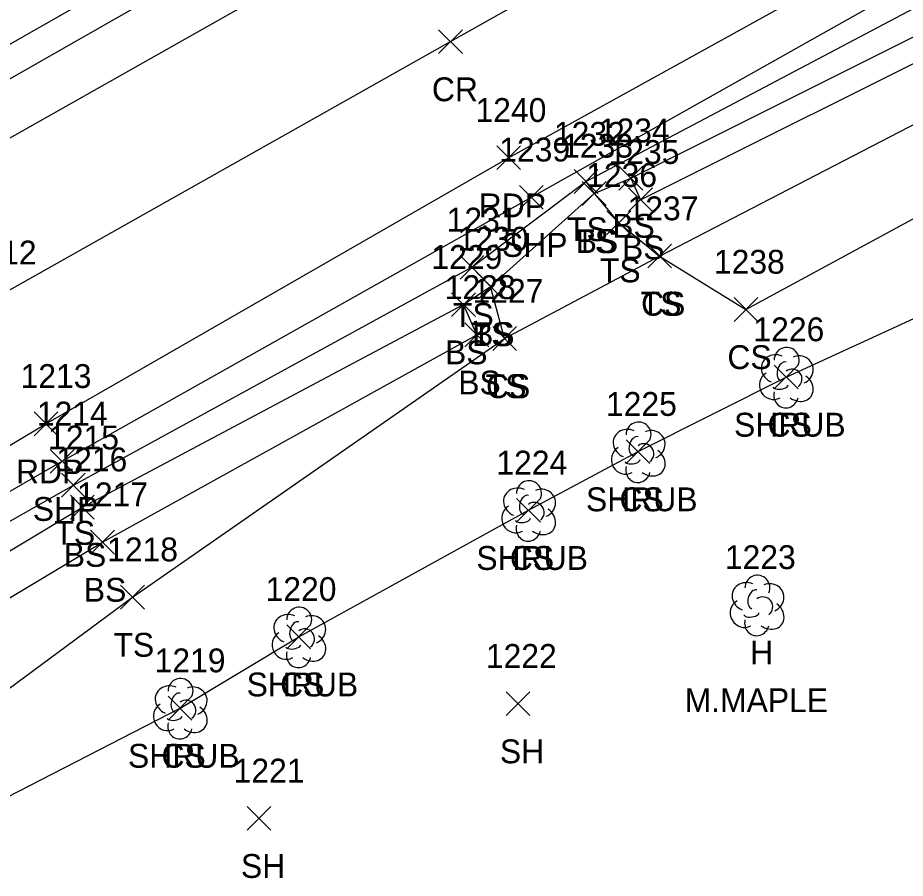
# Model space of a CAD drawing. Extents: x 1606530 to 1613020, y 784959 to 789666.
# Drawn here: x 1608865.5 to 1608940, y 788252.4 to 788324.6 of the extents above; entities that cross this region are included whole.
import ezdxf

# ---------------------------------------------------------------- set-up
doc = ezdxf.new("R2010")
doc.units = 0
for name, color, linetype in [('L_A', 7, 'Continuous'), ('L_C', 7, 'Continuous'), ('L_I', 7, 'Continuous'), ('L_TIC', 7, 'Continuous'), ('LELB', 7, 'Continuous'), ('LSH', 7, 'Continuous'), ('LTD', 7, 'Continuous'), ('P_A', 7, 'Continuous'), ('P_I', 7, 'Continuous'), ('P_TIC', 7, 'Continuous'), ('PET', 7, 'Continuous'), ('PRC', 7, 'Continuous'), ('PSP', 7, 'Continuous')]:
    doc.layers.add(name, color=color, linetype=linetype)

msp = doc.modelspace()

# ---------------------------------------------------------------- linework, layer by layer
at = {"layer": 'L_TIC'}
for points in [[(1608912.174, 788309.86), (1608914.174, 788311.86)], [(1608914.174, 788309.86), (1608912.174, 788311.86)], [(1608912.174, 788309.86), (1608914.174, 788311.86)], [(1608914.174, 788309.86), (1608912.174, 788311.86)], [(1608915.937, 788310.145), (1608917.937, 788312.145)], [(1608917.937, 788310.145), (1608915.937, 788312.145)], [(1608915.937, 788310.145), (1608917.937, 788312.145)], [(1608917.937, 788310.145), (1608915.937, 788312.145)], [(1608912.863, 788308.861), (1608914.863, 788310.861)], [(1608914.863, 788308.861), (1608912.863, 788310.861)], [(1608912.863, 788308.861), (1608914.863, 788310.861)], [(1608914.863, 788308.861), (1608912.863, 788310.861)], [(1608916.754, 788308.334), (1608918.754, 788310.334)], [(1608918.754, 788308.334), (1608916.754, 788310.334)], [(1608914.932, 788306.405), (1608916.932, 788308.405)], [(1608916.932, 788306.405), (1608914.932, 788308.405)], [(1608918.354, 788303.61), (1608920.354, 788305.61)], [(1608920.354, 788303.61), (1608918.354, 788305.61)], [(1608918.354, 788303.61), (1608920.354, 788305.61)], [(1608920.354, 788303.61), (1608918.354, 788305.61)], [(1608902.607, 788302.663), (1608904.607, 788304.663)], [(1608904.607, 788302.663), (1608902.607, 788304.663)], [(1608902.607, 788302.663), (1608904.607, 788304.663)], [(1608904.607, 788302.663), (1608902.607, 788304.663)], [(1608904.174, 788301.06), (1608906.174, 788303.06)], [(1608906.174, 788301.06), (1608904.174, 788303.06)], [(1608904.174, 788301.06), (1608906.174, 788303.06)], [(1608906.174, 788301.06), (1608904.174, 788303.06)], [(1608901.903, 788299.531), (1608903.903, 788301.531)], [(1608903.903, 788299.531), (1608901.903, 788301.531)], [(1608901.903, 788299.531), (1608903.903, 788301.531)], [(1608903.903, 788299.531), (1608901.903, 788301.531)], [(1608925.596, 788299.128), (1608927.596, 788301.128)], [(1608927.596, 788299.128), (1608925.596, 788301.128)], [(1608903.013, 788296.997), (1608905.013, 788298.997)], [(1608905.013, 788296.997), (1608903.013, 788298.997)], [(1608905.345, 788296.69), (1608907.345, 788298.69)], [(1608907.345, 788296.69), (1608905.345, 788298.69)], [(1608905.345, 788296.69), (1608907.345, 788298.69)], [(1608907.345, 788296.69), (1608905.345, 788298.69)], [(1608928.967, 788293.463), (1608930.967, 788295.463)], [(1608930.967, 788293.463), (1608928.967, 788295.463)], [(1608916.542, 788287.203), (1608918.542, 788289.203)], [(1608918.542, 788287.203), (1608916.542, 788289.203)], [(1608869.165, 788284.39), (1608871.165, 788286.39)], [(1608871.165, 788284.39), (1608869.165, 788286.39)], [(1608869.917, 788282.544), (1608871.917, 788284.544)], [(1608871.917, 788282.544), (1608869.917, 788284.544)], [(1608907.345, 788282.283), (1608909.345, 788284.283)], [(1608909.345, 788282.283), (1608907.345, 788284.283)], [(1608871.6, 788279.617), (1608873.6, 788281.617)], [(1608873.6, 788279.617), (1608871.6, 788281.617)], [(1608874.117, 788275.001), (1608876.117, 788277.001)], [(1608876.117, 788275.001), (1608874.117, 788277.001)], [(1608888.068, 788271.674), (1608890.068, 788273.674)], [(1608890.068, 788271.674), (1608888.068, 788273.674)], [(1608878.114, 788265.692), (1608880.114, 788267.692)], [(1608880.114, 788265.692), (1608878.114, 788267.692)], [(1608906.464, 788266.065), (1608908.464, 788268.065)], [(1608908.464, 788266.065), (1608906.464, 788268.065)], [(1608884.736, 788256.449), (1608886.736, 788258.449)], [(1608886.736, 788256.449), (1608884.736, 788258.449)]]:
    msp.add_lwpolyline(points, dxfattribs=at)
at = {"layer": 'LELB'}
for points in [[(1608830.696, 788263.063), (1608870.165, 788285.39), (1608903.607, 788303.663), (1608913.174, 788310.86), (1608944.686, 788327.514), (1608982.087, 788348.333), (1609025.652, 788367.839), (1609062.434, 788383.436), (1609080.361, 788388.448), (1609093.562, 788391.85), (1609111.494, 788398.335), (1609124.294, 788403.549), (1609165.327, 788413.887), (1609196.534, 788419.382), (1609241.91, 788424.939), (1609287.826, 788428.62), (1609331.16, 788428.802), (1609379.004, 788428.227), (1609424.692, 788425.716), (1609443.901, 788424.449), (1609475.845, 788418.568), (1609486.477, 788419.986), (1609502.626, 788421.703)], [(1608831.711, 788260.016), (1608870.917, 788283.544), (1608902.903, 788300.531), (1608905.174, 788302.06), (1608913.863, 788309.861), (1608916.937, 788311.145), (1608945.63, 788325.493), (1608982.977, 788345.361), (1609026.683, 788366.486), (1609062.425, 788381.051), (1609095.627, 788388.111), (1609108.106, 788392.394), (1609116.71, 788392.112), (1609124.652, 788392.268)], [(1608916.937, 788311.145), (1608917.754, 788309.334), (1608946.535, 788323.696), (1608983.532, 788344.076), (1609027.167, 788365.399), (1609062.769, 788379.31), (1609096.646, 788386.547), (1609108.627, 788390.006), (1609115.481, 788389.157)], [(1608913.174, 788310.86), (1608913.863, 788309.861), (1608915.932, 788307.405), (1608919.354, 788304.61), (1608948.758, 788319.84), (1608984.788, 788341.433), (1609027.872, 788364.143), (1609064.518, 788375.718), (1609081.683, 788376.845), (1609097.263, 788381.318)], [(1608906.345, 788297.69), (1608919.354, 788304.61), (1608926.596, 788300.128), (1608951.558, 788313.661), (1608958.57, 788316.223), (1608987.922, 788332.405), (1609030.947, 788357.96), (1609064.344, 788369.211), (1609081.683, 788376.845)], [(1608853.861, 788253.713), (1608879.114, 788266.692), (1608889.068, 788272.674), (1608908.345, 788283.283), (1608917.542, 788288.203), (1608929.967, 788294.463), (1608949.674, 788303.496), (1608962.876, 788306.16), (1608991.964, 788321.509), (1609035.123, 788349.675), (1609066.903, 788360.544), (1609090.163, 788369.421)], [(1608811.684, 788290.669), (1608854.482, 788316.493), (1608894.214, 788339.177), (1608933.711, 788362.091)], [(1608849.379, 788256.992), (1608875.117, 788276.001), (1608906.345, 788297.69), (1608905.174, 788302.06), (1608903.607, 788303.663)], [(1608833.879, 788257.4), (1608872.6, 788280.617), (1608904.013, 788297.997), (1608902.903, 788300.531)]]:
    msp.add_lwpolyline(points, dxfattribs=at)
at = {"layer": 'LSH'}
for p, q in [((1608929.967, 788294.463), (1608929.967, 788294.463)), ((1608929.967, 788294.463), (1608929.967, 788294.463)), ((1608917.542, 788288.203), (1608917.542, 788288.203)), ((1608917.542, 788288.203), (1608917.542, 788288.203)), ((1608908.345, 788283.283), (1608908.345, 788283.283)), ((1608908.345, 788283.283), (1608908.345, 788283.283)), ((1608889.068, 788272.674), (1608889.068, 788272.674)), ((1608889.068, 788272.674), (1608889.068, 788272.674)), ((1608879.114, 788266.692), (1608879.114, 788266.692)), ((1608879.114, 788266.692), (1608879.114, 788266.692))]:
    msp.add_line(p, q, dxfattribs=at)
for centre in [(1608930.013, 788295.897), (1608917.589, 788289.637), (1608908.392, 788284.717), (1608889.115, 788274.108), (1608879.16, 788268.126)]:
    msp.add_arc(centre, 1.047, 335.52715, 180.95627, dxfattribs=at)
for centre, major_axis, ratio, start_param, end_param in [((1608929.175, 788295.13), (1.21, -0.512), 0.895232, 1.570796, 4.712389), ((1608929.758, 788294.921), (-0.208, -0.792), 0.645439, 3.141593, 6.283185), ((1608931.008, 788295.047), (-1.141, -0.483), 0.949671, 1.570796, 4.712389), ((1608930.467, 788294.297), (-0.5, 0.667), 0.989748, 3.141593, 6.283185), ((1608928.883, 788293.755), (0.584, -1.042), 0.959034, 3.141593, 6.283185), ((1608930.967, 788293.63), (-1.09, 0.792), 0.841452, 1.570796, 4.712389), ((1608929.508, 788293.713), (-0.625, -0.083), 0.423636, 0, 3.141593), ((1608929.967, 788292.963), (0.265, 1.061), 0.942809, 1.570796, 4.712389), ((1608916.751, 788288.87), (1.21, -0.512), 0.895232, 1.570796, 4.712389), ((1608918.584, 788288.787), (-1.141, -0.483), 0.949671, 1.570796, 4.712389), ((1608917.334, 788288.662), (-0.208, -0.792), 0.645439, 3.141593, 6.283185), ((1608916.459, 788287.495), (0.584, -1.042), 0.959034, 3.141593, 6.283185), ((1608918.042, 788288.037), (-0.5, 0.667), 0.989748, 3.141593, 6.283185), ((1608918.543, 788287.37), (-1.09, 0.792), 0.841452, 1.570796, 4.712389), ((1608917.543, 788286.703), (0.265, 1.061), 0.942809, 1.570796, 4.712389), ((1608917.084, 788287.453), (-0.625, -0.083), 0.423636, 0, 3.141593), ((1608907.553, 788283.949), (1.21, -0.512), 0.895232, 1.570796, 4.712389), ((1608908.137, 788283.741), (-0.208, -0.792), 0.645439, 3.141593, 6.283185), ((1608909.386, 788283.866), (-1.141, -0.483), 0.949671, 1.570796, 4.712389), ((1608908.845, 788283.116), (-0.5, 0.667), 0.989748, 3.141593, 6.283185), ((1608907.262, 788282.574), (0.584, -1.042), 0.959034, 3.141593, 6.283185), ((1608909.345, 788282.45), (-1.09, 0.792), 0.841452, 1.570796, 4.712389), ((1608907.887, 788282.533), (-0.625, -0.083), 0.423636, 0, 3.141593), ((1608908.345, 788281.783), (0.265, 1.061), 0.942809, 1.570796, 4.712389), ((1608888.276, 788273.34), (1.21, -0.512), 0.895232, 1.570796, 4.712389), ((1608890.11, 788273.257), (-1.141, -0.483), 0.949671, 1.570796, 4.712389), ((1608888.86, 788273.132), (-0.208, -0.792), 0.645439, 3.141593, 6.283185), ((1608889.568, 788272.507), (-0.5, 0.667), 0.989748, 3.141593, 6.283185), ((1608887.985, 788271.965), (0.584, -1.042), 0.959034, 3.141593, 6.283185), ((1608890.068, 788271.84), (-1.09, 0.792), 0.841452, 1.570796, 4.712389), ((1608888.61, 788271.924), (-0.625, -0.083), 0.423636, 0, 3.141593), ((1608889.068, 788271.174), (0.265, 1.061), 0.942809, 1.570796, 4.712389), ((1608878.322, 788267.359), (1.21, -0.512), 0.895232, 1.570796, 4.712389), ((1608880.155, 788267.276), (-1.141, -0.483), 0.949671, 1.570796, 4.712389), ((1608878.905, 788267.15), (-0.208, -0.792), 0.645439, 3.141593, 6.283185), ((1608878.03, 788265.983), (0.584, -1.042), 0.959034, 3.141593, 6.283185), ((1608879.614, 788266.525), (-0.5, 0.667), 0.989748, 3.141593, 6.283185), ((1608880.114, 788265.859), (-1.09, 0.792), 0.841452, 1.570796, 4.712389), ((1608878.655, 788265.942), (-0.625, -0.083), 0.423636, 0, 3.141593), ((1608879.114, 788265.192), (0.265, 1.061), 0.942809, 1.570796, 4.712389)]:
    msp.add_ellipse(centre, major_axis=major_axis, ratio=ratio, start_param=start_param, end_param=end_param, dxfattribs=at)
at = {"layer": 'LTD'}
msp.add_line((1608927.515, 788275.352), (1608927.515, 788275.352), dxfattribs=at)
msp.add_line((1608927.515, 788275.352), (1608927.515, 788275.352), dxfattribs=at)
msp.add_arc((1608927.561, 788276.786), 1.047, 335.52715, 180.95627, dxfattribs=at)
for centre, major_axis, ratio, start_param, end_param in [((1608926.723, 788276.018), (1.21, -0.512), 0.895232, 1.570796, 4.712389), ((1608928.556, 788275.935), (-1.141, -0.483), 0.949671, 1.570796, 4.712389), ((1608927.306, 788275.81), (-0.208, -0.792), 0.645439, 3.141593, 6.283185), ((1608926.431, 788274.643), (0.584, -1.042), 0.959034, 3.141593, 6.283185), ((1608928.015, 788275.185), (-0.5, 0.667), 0.989748, 3.141593, 6.283185), ((1608928.515, 788274.518), (-1.09, 0.792), 0.841452, 1.570796, 4.712389), ((1608927.056, 788274.601), (-0.625, -0.083), 0.423636, 0, 3.141593), ((1608927.515, 788273.852), (0.265, 1.061), 0.942809, 1.570796, 4.712389)]:
    msp.add_ellipse(centre, major_axis=major_axis, ratio=ratio, start_param=start_param, end_param=end_param, dxfattribs=at)
at = {"layer": 'P_TIC'}
for points in [[(1608900.811, 788321.596), (1608902.811, 788323.596)], [(1608902.811, 788321.596), (1608900.811, 788323.596)], [(1608905.681, 788311.856), (1608907.681, 788313.856)], [(1608907.681, 788311.856), (1608905.681, 788313.856)], [(1608907.593, 788308.539), (1608909.593, 788310.539)], [(1608909.593, 788308.539), (1608907.593, 788310.539)], [(1608866.859, 788289.541), (1608868.859, 788291.541)], [(1608868.859, 788289.541), (1608866.859, 788291.541)], [(1608868.22, 788286.395), (1608870.22, 788288.395)], [(1608870.22, 788286.395), (1608868.22, 788288.395)]]:
    msp.add_lwpolyline(points, dxfattribs=at)
at = {"layer": 'PET'}
for points in [[(1608827.199, 788266.245), (1608867.859, 788290.541), (1608906.681, 788312.856), (1608942.677, 788332.755), (1608980.541, 788352.164), (1609023.571, 788373.225), (1609061.437, 788389.904), (1609090.798, 788401.175), (1609121.915, 788410.089), (1609165.169, 788419.998), (1609195.853, 788425.54), (1609240.139, 788431.13), (1609287.877, 788434.372), (1609331.481, 788435.115), (1609378.889, 788434.051), (1609425.427, 788432.251), (1609443.83, 788431.331), (1609477.321, 788429.782), (1609518.441, 788427.602), (1609569.185, 788424.684), (1609602.993, 788422.58), (1609641.45, 788420.372), (1609681.697, 788417.919), (1609727.381, 788415.531)], [(1608858.102, 788310.732), (1608896.559, 788332.458), (1608932.583, 788352.682), (1608960.396, 788367.207), (1608987.919, 788381.261), (1609019.358, 788396.212), (1609040.554, 788405.359), (1609066.482, 788415.581), (1609102.049, 788427.759), (1609127.707, 788434.803)]]:
    msp.add_lwpolyline(points, dxfattribs=at)
at = {"layer": 'PRC'}
msp.add_lwpolyline([(1608863.252, 788300.903), (1608901.811, 788322.596), (1608937.609, 788342.722), (1608976.118, 788362.757), (1609017.577, 788382.951), (1609062.579, 788402.235), (1609089.789, 788412.891), (1609118.805, 788421.444), (1609162.845, 788431.752), (1609194.146, 788437.356), (1609237.64, 788442.85), (1609286.897, 788446.16), (1609332.711, 788446.436), (1609379.393, 788445.342), (1609425.621, 788443.432), (1609445.831, 788442.47), (1609477.779, 788440.947), (1609519.757, 788438.847), (1609569.723, 788435.898), (1609601.73, 788434.311), (1609642.39, 788431.817), (1609682.025, 788429.153), (1609726.546, 788426.785)], dxfattribs=at)
at = {"layer": 'PSP'}
for points in [[(1608855.389, 788314.113), (1608894.808, 788336.591), (1608931.247, 788356.378), (1608958.599, 788370.933), (1608985.981, 788385.272), (1609018.034, 788400.244), (1609039.035, 788409.707), (1609065.41, 788420.262), (1609085.948, 788428.615), (1609114.118, 788436.455)], [(1608830.356, 788264.996), (1608869.22, 788287.395), (1608908.593, 788309.539), (1608943.858, 788329.41), (1608981.495, 788349.27), (1609025.121, 788370.206), (1609061.921, 788386.228), (1609076.386, 788391.443), (1609089.956, 788397.157), (1609122.924, 788407.129), (1609165.713, 788417.027), (1609196.423, 788422.444), (1609241.306, 788428.683), (1609287.876, 788431.577), (1609331.197, 788431.668), (1609378.916, 788430.276), (1609425.006, 788428.307)]]:
    msp.add_lwpolyline(points, dxfattribs=at)

# ---------------------------------------------------------------- texts
at = {"layer": 'L_A'}
for s, p in [('TS', (1608911.584, 788305.86)), ('TS', (1608911.584, 788305.86)), ('BS', (1608915.378, 788306.145)), ('BS', (1608915.378, 788306.145)), ('TS', (1608912.273, 788304.861)), ('BS', (1608912.304, 788304.861)), ('BS', (1608916.195, 788304.334)), ('TS', (1608914.341, 788302.405)), ('TS', (1608917.763, 788299.61)), ('CS', (1608917.795, 788299.61)), ('TS', (1608902.016, 788298.663)), ('TS', (1608902.016, 788298.663)), ('TS', (1608903.584, 788297.06)), ('BS', (1608903.615, 788297.06)), ('BS', (1608901.344, 788295.531)), ('BS', (1608901.344, 788295.531)), ('CS', (1608925.037, 788295.128)), ('BS', (1608902.454, 788292.997)), ('TS', (1608904.755, 788292.69)), ('CS', (1608904.786, 788292.69)), ('SHRUB', (1608925.597, 788289.463)), ('CS', (1608928.408, 788289.463)), ('SHRUB', (1608913.172, 788283.203)), ('CS', (1608915.983, 788283.203)), ('TS', (1608868.574, 788280.39)), ('BS', (1608869.358, 788278.544)), ('SHRUB', (1608903.975, 788278.283)), ('CS', (1608906.786, 788278.283)), ('BS', (1608871.041, 788275.617)), ('TS', (1608873.526, 788271.001)), ('H', (1608926.948, 788270.352)), ('SHRUB', (1608884.698, 788267.674)), ('CS', (1608887.509, 788267.674)), ('SH', (1608905.952, 788262.065)), ('SHRUB', (1608874.744, 788261.692)), ('CS', (1608877.555, 788261.692)), ('SH', (1608884.224, 788252.449))]:
    msp.add_text(s, height=2, dxfattribs=at).set_placement(p)
at = {"layer": 'L_C'}
msp.add_text('M.MAPLE', height=2, dxfattribs=at).set_placement((1608921.452, 788266.352))
at = {"layer": 'L_I'}
for s, p in [('1232', (1608910.482, 788313.86)), ('1232', (1608910.482, 788313.86)), ('1234', (1608914.245, 788314.145)), ('1234', (1608914.245, 788314.145)), ('1233', (1608911.171, 788312.861)), ('1233', (1608911.171, 788312.861)), ('1235', (1608915.061, 788312.334)), ('1236', (1608913.184, 788310.405)), ('1237', (1608916.661, 788307.61)), ('1237', (1608916.661, 788307.61)), ('1231', (1608901.481, 788306.663)), ('1231', (1608901.481, 788306.663)), ('1230', (1608902.395, 788305.06)), ('1230', (1608902.395, 788305.06)), ('1229', (1608900.203, 788303.531)), ('1229', (1608900.203, 788303.531)), ('1238', (1608923.903, 788303.128)), ('1228', (1608901.32, 788300.997)), ('1227', (1608903.653, 788300.69)), ('1227', (1608903.653, 788300.69)), ('1226', (1608927.219, 788297.463)), ('1226', (1608927.219, 788297.463)), ('1225', (1608914.85, 788291.203)), ('1225', (1608914.85, 788291.203)), ('1215', (1608868.039, 788288.39)), ('1216', (1608868.736, 788286.544)), ('1224', (1608905.652, 788286.283)), ('1224', (1608905.652, 788286.283)), ('1217', (1608870.474, 788283.617)), ('1218', (1608872.991, 788279.001)), ('1223', (1608924.822, 788278.352)), ('1220', (1608886.289, 788275.674)), ('1220', (1608886.289, 788275.674)), ('1222', (1608904.771, 788270.065)), ('1219', (1608876.98, 788269.692)), ('1219', (1608876.98, 788269.692)), ('1221', (1608883.61, 788260.449))]:
    msp.add_text(s, height=2, dxfattribs=at).set_placement(p)
at = {"layer": 'P_A'}
for s, p in [('CR', (1608900.244, 788317.596)), ('RDP', (1608904.169, 788307.856)), ('SHP', (1608906.128, 788304.539)), ('RDP', (1608865.347, 788285.541)), ('SHP', (1608866.756, 788282.395))]:
    msp.add_text(s, height=2, dxfattribs=at).set_placement(p)
at = {"layer": 'P_I'}
for s, p in [('1240', (1608903.902, 788315.856)), ('1239', (1608905.892, 788312.539)), ('1212', (1608861.126, 788303.903)), ('1213', (1608865.733, 788293.541)), ('1214', (1608867.095, 788290.395))]:
    msp.add_text(s, height=2, dxfattribs=at).set_placement(p)

doc.saveas('drawing.dxf')
